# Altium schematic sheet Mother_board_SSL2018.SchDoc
size A4
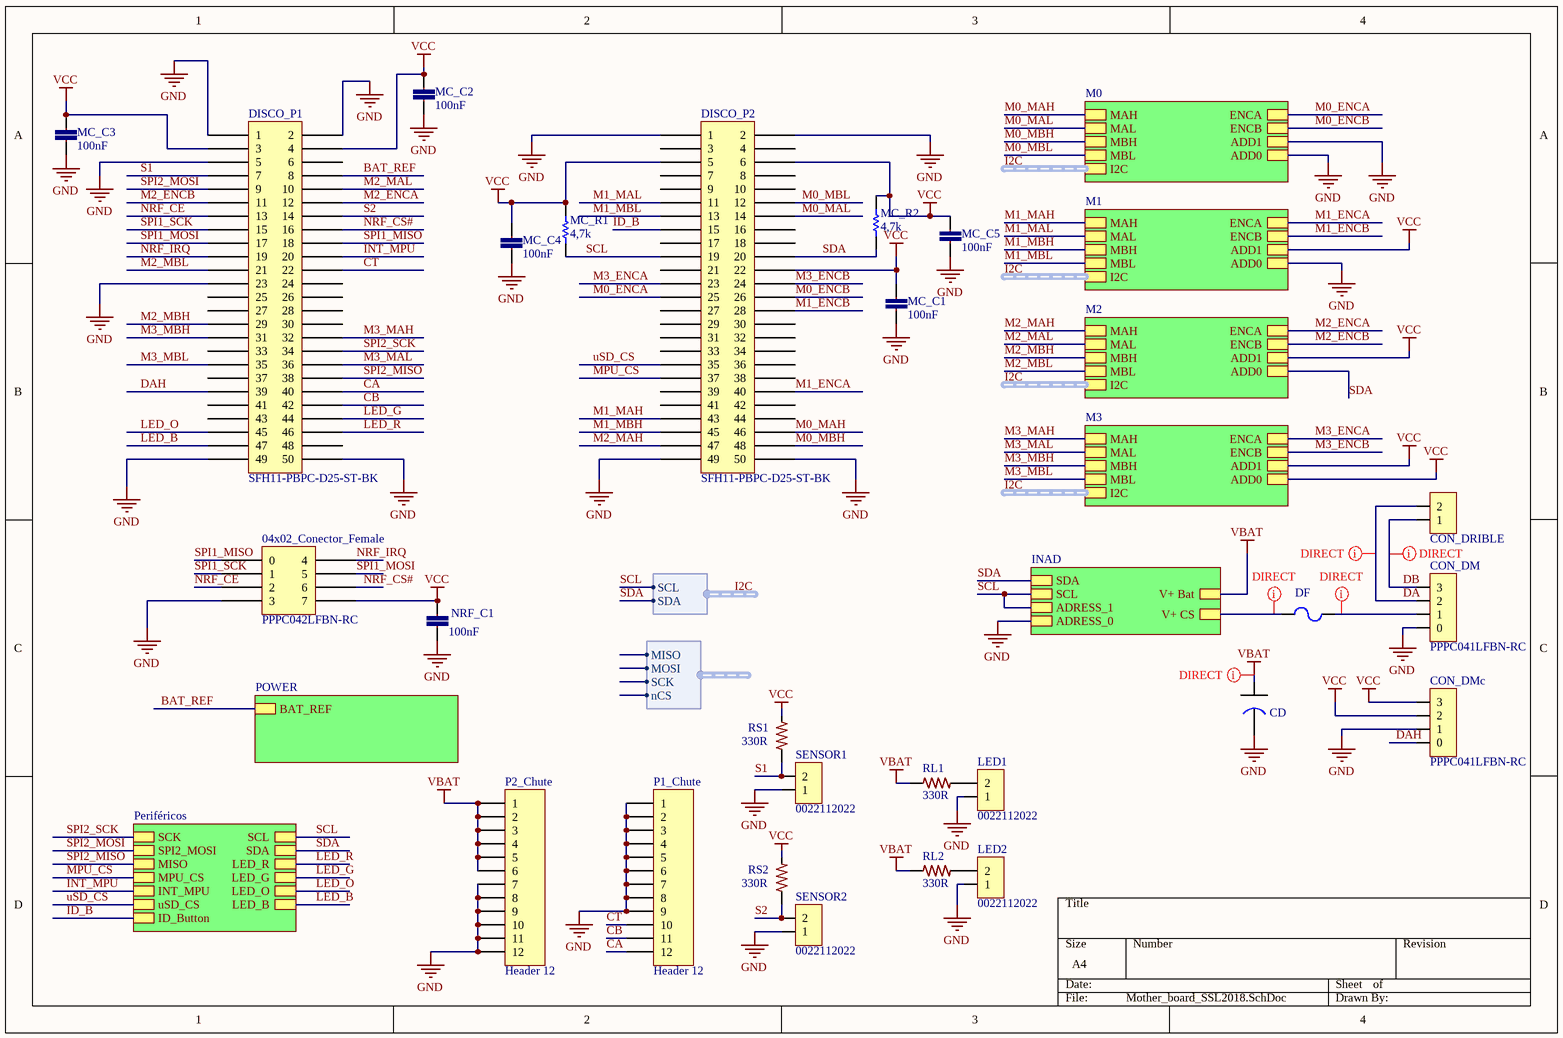
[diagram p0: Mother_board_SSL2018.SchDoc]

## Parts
04x02_Conector_Female  PPPC042LFBN-RC  [04x02_Conector_Female]
CD  EEE-FK1C681GP  [EEE-FK1C681GP]  (value not drawn)
CON_DM  PPPC041LFBN-RC  [04x01_Conector_Female - duplicate]
CON_DMc  PPPC041LFBN-RC  [04x01_Conector_Female - duplicate]
CON_DRIBLE  0022112022  [02x01_Conector_Male]  (value not drawn)
DF  MF-MSMF250/16X  [RESC4632X16N]  (value not drawn)
DISCO_P1  SFH11-PBPC-D25-ST-BK  [25x02_Conector_Female]
DISCO_P2  SFH11-PBPC-D25-ST-BK  [25x02_Conector_Female]
LED1  0022112022  [02x01_Conector_Male]
LED2  0022112022  [02x01_Conector_Male]
MC_C1  100nF  [0402-CAP]
MC_C2  100nF  [0402-CAP]
MC_C3  100nF  [0402-CAP]
MC_C4  100nF  [0402-CAP]
MC_C5  100nF  [0402-CAP]
MC_R1  4,7k  [0402]
MC_R2  4,7k  [0402]
NRF_C1  100nF  [0402-CAP]
P1_Chute  Header 12  [HDR1X12]
P2_Chute  Header 12  [HDR1X12]
RL1  330R  [0402-RES-HD]
RL2  330R  [0402-RES-HD]
RS1  330R  [0402-RES-HD]
RS2  330R  [0402-RES-HD]
SENSOR1  0022112022  [02x01_Conector_Male]
SENSOR2  0022112022  [02x01_Conector_Male]

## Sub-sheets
INAD = INA220.SchDoc: V+ Bat, SDA, SCL, ADRESS_1, ADRESS_0, V+ CS
M0 = MOTORES.SchDoc: MBH, MAH, MBL, MAL, I2C (harness I2C), ENCA, ENCB, ADD1, ADD0
M1 = MOTORES.SchDoc: MBH, MAH, MBL, MAL, I2C (harness I2C), ENCA, ENCB, ADD1, ADD0
M2 = MOTORES.SchDoc: MBH, MAH, MBL, MAL, I2C (harness I2C), ENCA, ENCB, ADD1, ADD0
M3 = MOTORES.SchDoc: MBH, MAH, MBL, MAL, I2C (harness I2C), ENCA, ENCB, ADD1, ADD0
Periféricos = Periféricos.SchDoc: SCK, SPI2_MOSI, MPU_CS, MISO, INT_MPU, uSD_CS, SCL, SDA, LED_R, LED_G, LED_O, LED_B, ID_Button
POWER = POWER.SchDoc: BAT_REF

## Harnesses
I2C: SCL, SDA
I2C: MISO, MOSI, SCK, nCS

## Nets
GND: 04x02_Conector_Female.3 CD.2 CON_DM.0 CON_DMc.1 DISCO_P1.1 DISCO_P1.2 DISCO_P1.5 DISCO_P1.23 DISCO_P1.49 DISCO_P1.50 DISCO_P2.1 DISCO_P2.2 DISCO_P2.49 DISCO_P2.50 LED1.1 LED2.1 MC_C1.1 MC_C2.1 MC_C3.2 MC_C4.1 MC_C5.1 NRF_C1.2 P1_Chute.1 P1_Chute.2 P1_Chute.3 P1_Chute.4 P1_Chute.5 P1_Chute.6 P1_Chute.7 P1_Chute.8 P1_Chute.9 P2_Chute.7 P2_Chute.8 P2_Chute.9 P2_Chute.10 P2_Chute.11 P2_Chute.12 SENSOR1.1 SENSOR2.1 ; sheet M0/ADD1, sheet M0/ADD0, sheet M1/ADD0, sheet INAD/ADRESS_0
VBAT: CD.1 P2_Chute.1 P2_Chute.2 P2_Chute.3 P2_Chute.4 P2_Chute.5 P2_Chute.6 RL1.1 RL2.1 ; sheet INAD/V+ Bat
VCC: 04x02_Conector_Female.7 CON_DMc.2 CON_DMc.3 DISCO_P1.3 DISCO_P1.4 DISCO_P2.5 DISCO_P2.6 DISCO_P2.22 MC_C1.2 MC_C2.2 MC_C3.1 MC_C4.2 MC_C5.2 MC_R1.2 MC_R2.2 NRF_C1.1 RS1.2 RS2.2 ; sheet M1/ADD1, sheet M2/ADD1, sheet M3/ADD1, sheet M3/ADD0
BAT_REF: DISCO_P1.8 ; sheet POWER/BAT_REF
CA: DISCO_P1.40 P1_Chute.12
CB: DISCO_P1.42 P1_Chute.11
CT: DISCO_P1.22 P1_Chute.10
DA: CON_DM.2 CON_DRIBLE.2
DAH: CON_DMc.0 DISCO_P1.39
DB: CON_DM.3 CON_DRIBLE.1
ID_B: DISCO_P2.15 ; sheet Periféricos/ID_Button
INT_MPU: DISCO_P1.20 ; sheet Periféricos/INT_MPU
LED_B: DISCO_P1.47 ; sheet Periféricos/LED_B
LED_G: DISCO_P1.44 ; sheet Periféricos/LED_G
LED_O: DISCO_P1.45 ; sheet Periféricos/LED_O
LED_R: DISCO_P1.46 ; sheet Periféricos/LED_R
M0_ENCA: DISCO_P2.25 ; sheet M0/ENCA
M0_ENCB: DISCO_P2.26 ; sheet M0/ENCB
M0_MAH: DISCO_P2.46 ; sheet M0/MAH
M0_MAL: DISCO_P2.14 ; sheet M0/MAL
M0_MBH: DISCO_P2.48 ; sheet M0/MBH
M0_MBL: DISCO_P2.12 ; sheet M0/MBL
M1_ENCA: DISCO_P2.40 ; sheet M1/ENCA
M1_ENCB: DISCO_P2.28 ; sheet M1/ENCB
M1_MAH: DISCO_P2.43 ; sheet M1/MAH
M1_MAL: DISCO_P2.11 ; sheet M1/MAL
M1_MBH: DISCO_P2.45 ; sheet M1/MBH
M1_MBL: DISCO_P2.13 ; sheet M1/MBL
M2_ENCA: DISCO_P1.12 ; sheet M2/ENCA
M2_ENCB: DISCO_P1.11 ; sheet M2/ENCB
M2_MAH: DISCO_P2.47 ; sheet M2/MAH
M2_MAL: DISCO_P1.10 ; sheet M2/MAL
M2_MBH: DISCO_P1.29 ; sheet M2/MBH
M2_MBL: DISCO_P1.21 ; sheet M2/MBL
M3_ENCA: DISCO_P2.23 ; sheet M3/ENCA
M3_ENCB: DISCO_P2.24 ; sheet M3/ENCB
M3_MAH: DISCO_P1.32 ; sheet M3/MAH
M3_MAL: DISCO_P1.36 ; sheet M3/MAL
M3_MBH: DISCO_P1.31 ; sheet M3/MBH
M3_MBL: DISCO_P1.35 ; sheet M3/MBL
MPU_CS: DISCO_P2.37 ; sheet Periféricos/MPU_CS
NRF_CE: 04x02_Conector_Female.2 DISCO_P1.13
NRF_CS#: 04x02_Conector_Female.6 DISCO_P1.16
NRF_IRQ: 04x02_Conector_Female.4 DISCO_P1.19
S1: DISCO_P1.7 RS1.1 SENSOR1.2
S2: DISCO_P1.14 RS2.1 SENSOR2.2
SCL: DISCO_P2.19 MC_R1.1 ; sheet INAD/SCL, sheet INAD/ADRESS_1, sheet Periféricos/SCL, sheet M0/I2C.SCL  [project net I2C.SCL]
SDA: DISCO_P2.20 MC_R2.1 ; sheet M2/ADD0, sheet INAD/SDA, sheet Periféricos/SDA, sheet M0/I2C.SDA  [project net I2C.SDA]
SPI1_MISO: 04x02_Conector_Female.0 DISCO_P1.18
SPI1_MOSI: 04x02_Conector_Female.5 DISCO_P1.17
SPI1_SCK: 04x02_Conector_Female.1 DISCO_P1.15
SPI2_MISO: DISCO_P1.38 ; sheet Periféricos/MISO
SPI2_MOSI: DISCO_P1.9 ; sheet Periféricos/SPI2_MOSI
SPI2_SCK: DISCO_P1.34 ; sheet Periféricos/SCK
uSD_CS: DISCO_P2.35 ; sheet Periféricos/uSD_CS
NetCON_DM_1: CON_DM.1 DF.1
NetDF_2: DF.2 ; sheet INAD/V+ CS
NetLED1_2: LED1.2 RL1.2
NetLED2_2: LED2.2 RL2.2

Not connected (* = marked no-connect by the designer): DISCO_P1 6 24 25 26 27 28 30 33 37 41 43 48; DISCO_P2 3 4 7 8 9 10 16 17 18 21 27 29 30 31 32 33 34 36 38 39 41 42 44

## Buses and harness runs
harness I2C = sheet M0/I2C
harness I2C = sheet M1/I2C
harness I2C = sheet M2/I2C
harness I2C = sheet M3/I2C

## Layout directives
net class DIRECT: DA, DB, NetCON_DM_1, NetDF_2, VBAT

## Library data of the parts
04x02_Conector_Female = 04x02_Conector_Female: 8 Position Header Connector 0.100" (2.54mm) Through Hole Gold
CD = CAP AL 680UF/16V: Aluminum Electrolytic Capacitors - SMD Al Lytic Cap SMT FK Series 105C
CON_DM CON_DMc = 04x01_Conector_Female-SCH: 4 Position Header Connector 0.100" (2.54mm) Through Hole Gold
CON_DRIBLE LED1 LED2 SENSOR1 SENSOR2 = 02x01_Conector_Male: CONN HEADER 2POS .100 VERT GOLD
DF = MF-MSMF250/16X-01.A.1: PTC RESETTABLE .30A 30V 1812
DISCO_P1 DISCO_P2 = 25x02_Conector_Female: 50 Position Header Connector 0.100" (2.54mm) Through Hole Gold
MC_C1-MC_C5 NRF_C1 = CC0402-100nF-A.12: CAP CER 0.1UF 10V 20% X5R 0402; Part No: VJ0402V104ZXQPBC; Cod EMS: 05.281.006.133; Value: 100n
MC_R1 MC_R2 = Res1: Resistor
P1_Chute P2_Chute = Header 12: Header, 12-Pin
RL1 RL2 RS1 RS2 = R0402-330R-7: RES 330 OHM 1/10W 1% 0402 SMD; Part No: ERJ-2RKF3300X; Value: 330; Cod EMS: 05.280.029.506; Family Description: RESISTOR FILME ESPESSO 10R-1M / 1/10W / 1% / 0402. P/N: ERJ-2RKF....X – PANASONIC ELECTRONIC COMPONENTS.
